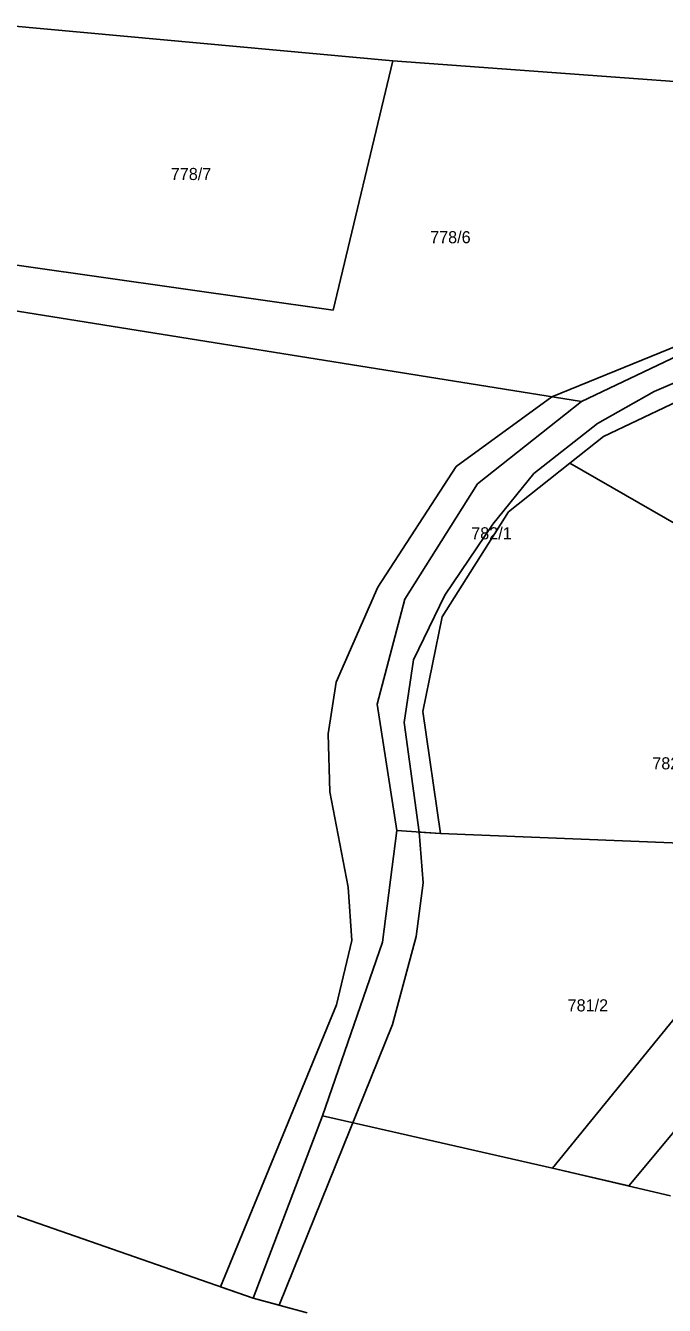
# Model space of a CAD drawing. Extents: x 7498273 to 7499989, y 5499795 to 5500810.
# Drawn here: x 7499202 to 7499281.1, y 5500521 to 5500679.6 of the extents above; entities that cross this region are included whole.
import ezdxf

# ---------------------------------------------------------------- set-up
doc = ezdxf.new("R2010")
doc.units = 0
for name, color, linetype in [('211-numer działki ewidencyjnej', 7, 'Continuous'), ('217-kontur klasyfikacyjny', 7, 'Continuous'), ('218-kontur użytku gruntowego', 7, 'Continuous'), ('219-działka ewidencyjna', 7, 'Continuous')]:
    doc.layers.add(name, color=color, linetype=linetype)

msp = doc.modelspace()

# ---------------------------------------------------------------- linework, layer by layer
at = {"layer": '217-kontur klasyfikacyjny'}
for points in [[(7499267.15, 5500633.61), (7499290.56, 5500643.13)], [(7499279.82, 5500634.24), (7499299.44, 5500642.68)], [(7499272.79, 5500630.29), (7499279.82, 5500634.24)], [(7499255.3, 5500624.96), (7499267.15, 5500633.61)], [(7499264.92, 5500624.08), (7499272.79, 5500630.29)], [(7499245.6, 5500610), (7499255.3, 5500624.96)], [(7499259.84, 5500617.81), (7499264.92, 5500624.08)], [(7499253.89, 5500609.03), (7499259.84, 5500617.81)], [(7499240.42, 5500598.22), (7499245.6, 5500610)], [(7499250.01, 5500601), (7499253.89, 5500609.03)], [(7499248.85, 5500593.23), (7499250.01, 5500601)], [(7499239.45, 5500591.81), (7499240.42, 5500598.22)], [(7499250.72, 5500579.64), (7499248.85, 5500593.23)], [(7499239.66, 5500584.63), (7499239.45, 5500591.81)], [(7499320.32, 5500588.2), (7499276.67, 5500535.79)], [(7499241.91, 5500572.82), (7499239.66, 5500584.63)], [(7499253.37, 5500579.46), (7499250.72, 5500579.64)], [(7499250.72, 5500579.64), (7499251.19, 5500573.35)], [(7499299.48, 5500577.61), (7499253.37, 5500579.46)], [(7499267.24, 5500538), (7499299.48, 5500577.61)], [(7499242.35, 5500566.2), (7499241.91, 5500572.82)], [(7499251.19, 5500573.35), (7499250.34, 5500566.71)], [(7499240.47, 5500558.23), (7499242.35, 5500566.2)], [(7499250.34, 5500566.71), (7499247.4, 5500555.78)], [(7499226.11, 5500523.27), (7499240.47, 5500558.23)], [(7499247.4, 5500555.78), (7499233.37, 5500521)], [(7499276.67, 5500535.79), (7499267.24, 5500538)], [(7499230.15, 5500521.86), (7499226.11, 5500523.27)], [(7499233.37, 5500521), (7499230.15, 5500521.86)]]:
    msp.add_lwpolyline(points, dxfattribs=at)
at = {"layer": '218-kontur użytku gruntowego'}
for points in [[(7499290.56, 5500643.13), (7499267.15, 5500633.61)], [(7499299.44, 5500642.68), (7499279.82, 5500634.24)], [(7499279.82, 5500634.24), (7499272.79, 5500630.29)], [(7499267.15, 5500633.61), (7499255.3, 5500624.96)], [(7499272.79, 5500630.29), (7499264.92, 5500624.08)], [(7499255.3, 5500624.96), (7499245.6, 5500610)], [(7499264.92, 5500624.08), (7499259.84, 5500617.81)], [(7499259.84, 5500617.81), (7499253.89, 5500609.03)], [(7499245.6, 5500610), (7499240.42, 5500598.22)], [(7499253.89, 5500609.03), (7499250.01, 5500601)], [(7499250.01, 5500601), (7499248.85, 5500593.23)], [(7499240.42, 5500598.22), (7499239.45, 5500591.81)], [(7499248.85, 5500593.23), (7499250.72, 5500579.64)], [(7499239.45, 5500591.81), (7499239.66, 5500584.63)], [(7499276.67, 5500535.79), (7499320.32, 5500588.2)], [(7499239.66, 5500584.63), (7499241.91, 5500572.82)], [(7499250.72, 5500579.64), (7499253.37, 5500579.46)], [(7499251.19, 5500573.35), (7499250.72, 5500579.64)], [(7499253.37, 5500579.46), (7499299.48, 5500577.61)], [(7499299.48, 5500577.61), (7499267.24, 5500538)], [(7499241.91, 5500572.82), (7499242.35, 5500566.2)], [(7499250.34, 5500566.71), (7499251.19, 5500573.35)], [(7499242.35, 5500566.2), (7499240.47, 5500558.23)], [(7499247.4, 5500555.78), (7499250.34, 5500566.71)], [(7499240.47, 5500558.23), (7499226.11, 5500523.27)], [(7499233.37, 5500521), (7499247.4, 5500555.78)], [(7499267.24, 5500538), (7499276.67, 5500535.79)], [(7499226.11, 5500523.27), (7499230.15, 5500521.86)], [(7499230.15, 5500521.86), (7499233.37, 5500521)]]:
    msp.add_lwpolyline(points, dxfattribs=at)
at = {"layer": '219-działka ewidencyjna'}
for points in [[(7499199.73, 5500679.61), (7499247.45, 5500675.23)], [(7499240.05, 5500644.33), (7499247.45, 5500675.23)], [(7499247.45, 5500675.23), (7499312.74, 5500670.46)], [(7499192.42, 5500651.11), (7499240.05, 5500644.33)], [(7499270.84, 5500633.02), (7499299.03, 5500646.43)], [(7499191.39, 5500645.74), (7499270.84, 5500633.02)], [(7499273.54, 5500628.66), (7499302.73, 5500642.54)], [(7499257.92, 5500622.79), (7499270.84, 5500633.02)], [(7499269.39, 5500625.36), (7499273.54, 5500628.66)], [(7499261.76, 5500619.34), (7499269.39, 5500625.36)], [(7499269.39, 5500625.36), (7499305.21, 5500604.75)], [(7499248.92, 5500608.53), (7499257.92, 5500622.79)], [(7499253.55, 5500606.31), (7499261.76, 5500619.34)], [(7499245.51, 5500595.49), (7499248.92, 5500608.53)], [(7499251.18, 5500594.59), (7499253.55, 5500606.31)], [(7499245.51, 5500595.49), (7499247.95, 5500579.84)], [(7499251.18, 5500594.59), (7499253.37, 5500579.46)], [(7499246.15, 5500565.99), (7499247.95, 5500579.84)], [(7499247.95, 5500579.84), (7499253.37, 5500579.46)], [(7499253.37, 5500579.46), (7499299.48, 5500577.61)], [(7499267.24, 5500538), (7499299.48, 5500577.61)], [(7499238.72, 5500544.48), (7499246.15, 5500565.99)], [(7499230.15, 5500521.86), (7499238.72, 5500544.48)], [(7499238.72, 5500544.48), (7499267.24, 5500538)], [(7499267.24, 5500538), (7499281.86, 5500534.57)], [(7499194.31, 5500534.37), (7499230.15, 5500521.86)], [(7499236.83, 5500520.07), (7499230.15, 5500521.86)]]:
    msp.add_lwpolyline(points, dxfattribs=at)

# ---------------------------------------------------------------- texts
at = {"layer": '211-numer działki ewidencyjnej'}
for s, p in [('778/7', (7499219.94, 5500660.47)), ('778/6', (7499252.07, 5500652.63)), ('782/1', (7499257.16, 5500615.93)), ('782/3', (7499279.59, 5500587.42)), ('781/2', (7499269.1, 5500557.42))]:
    msp.add_text(s, height=1.5, dxfattribs=at).set_placement(p)

doc.saveas('drawing.dxf')
